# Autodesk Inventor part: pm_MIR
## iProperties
Shininess: 64.0
Length Units: 11272
Angle Units: 11279
Time Units: 11290
Mass Units: 11286
Length Display Precision: 3
Angle Display Precision: 2
Compacted: True
Part Number: pm_MIR
Document SubType Name: Modeling
Created: 2004-08
Designer: John Blackburn
Material: Default
Manufacturer: Standard
Standards Organization: Custom
Density: 0.0
Volumn: 0.0
Area: 0.0
PropertySet Name: Model Information
Control State: 0
Master: False
Checked Out: False
Author: John Blackburn
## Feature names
1. Derived Body1 [Tagging]
